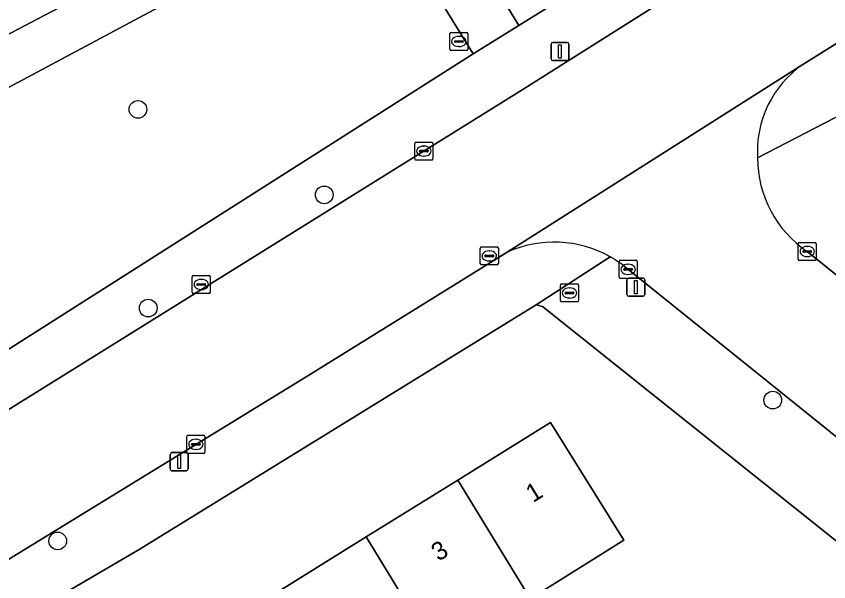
# Model space of a CAD drawing. Extents: x 159674 to 160531, y 382172 to 382904.
# Drawn here: x 160238.74 to 160283.66, y 382711.06 to 382742.32 of the extents above; entities that cross this region are included whole.
import ezdxf

# ---------------------------------------------------------------- set-up
doc = ezdxf.new("R2010")
doc.units = 0
for name, color, linetype in [('IMGEO_Boom', 7, 'Continuous'), ('IMGEO_Brandkraan', 7, 'Continuous'), ('IMGEO_Erf', 7, 'Continuous'), ('IMGEO_Groenvoorziening', 7, 'Continuous'), ('IMGEO_Kolk', 7, 'Continuous'), ('IMGEO_Lichtmast', 7, 'Continuous'), ('IMGEO_Pand', 7, 'Continuous'), ('IMGEO_Pand_nummerreeks', 7, 'Continuous'), ('IMGEO_Rijbaan_lokaal_open', 7, 'Continuous'), ('IMGEO_Rioolput', 7, 'Continuous'), ('IMGEO_Voetpad_halfverhard', 7, 'Continuous'), ('IMGEO_Voetpad_open', 7, 'Continuous')]:
    doc.layers.add(name, color=color, linetype=linetype)

msp = doc.modelspace()

# ---------------------------------------------------------------- linework, layer by layer
at = {"layer": 'IMGEO_Boom'}
for centre in [(160245.468, 382737.168), (160255.767, 382732.442), (160246.035, 382726.184), (160280.566, 382721.097), (160241.031, 382713.312)]:
    msp.add_circle(centre, 0.489, dxfattribs=at)
at = {"layer": 'IMGEO_Brandkraan'}
for p, q in [((160268.827, 382726.596), (160268.827, 382727.448)), ((160268.902, 382727.522), (160269.754, 382727.522)), ((160269.828, 382727.448), (160269.828, 382726.596)), ((160269.086, 382727.016), (160269.086, 382727.028)), ((160269.524, 382726.979), (160269.126, 382726.979)), ((160269.129, 382727.065), (160269.527, 382727.065)), ((160269.315, 382727.302), (160269.34, 382727.302)), ((160269.57, 382727.028), (160269.57, 382727.016)), ((160269.754, 382726.522), (160268.902, 382726.522)), ((160269.338, 382726.742), (160269.313, 382726.742))]:
    msp.add_line(p, q, dxfattribs=at)
for points in [[(160268.827, 382726.596), (160268.827, 382727.448)], [(160268.902, 382727.522), (160269.754, 382727.522)], [(160269.828, 382727.448), (160269.828, 382726.596)], [(160269.754, 382726.522), (160268.902, 382726.522)]]:
    msp.add_lwpolyline(points, dxfattribs=at)
for centre, radius, start, end in [((160268.904, 382727.446), 0.0765, 91.552, 178.448), ((160268.904, 382727.446), 0.0765, 91.552, 178.448), ((160269.752, 382727.446), 0.0765, 1.552, 88.448), ((160269.752, 382727.446), 0.0765, 1.552, 88.448), ((160269.126, 382727.025), 0.0403, 85.8775, 175.7526), ((160269.123, 382727.015), 0.0366, 178.938, 274.7102), ((160269.527, 382727.022), 0.043, 264.8664, 352.4533), ((160269.531, 382727.027), 0.0386, 1.7309, 96.639), ((160268.904, 382726.598), 0.0765, 181.552, 268.448), ((160268.904, 382726.598), 0.0765, 181.552, 268.448), ((160269.752, 382726.598), 0.0765, 271.552, 358.448), ((160269.752, 382726.598), 0.0765, 271.552, 358.448)]:
    msp.add_arc(centre, radius, start, end, dxfattribs=at)
for centre, major_axis, ratio, start_param, end_param in [((160269.314, 382727.022), (-0.387, 0.002), 0.722429, 4.712389, 7.853982), ((160269.339, 382727.022), (-0.39, 0.002), 0.717154, 1.570796, 4.712389)]:
    msp.add_ellipse(centre, major_axis=major_axis, ratio=ratio, start_param=start_param, end_param=end_param, dxfattribs=at)
at = {"layer": 'IMGEO_Erf'}
for points in [[(160263.63, 382697.299), (160266.891, 382692.05), (160272.972, 382696.028), (160269.707, 382701.284), (160271.793, 382702.58), (160273.825, 382703.842), (160277.09, 382698.586), (160280.422, 382700.656), (160288.011, 382710.171), (160267.842, 382726.279), (160267.481, 382726.359), (160260.898, 382722.304), (160245.542, 382712.846), (160232.632, 382705.313), (160223.268, 382700.381)], [(160237.854, 382700.968), (160242.783, 382704.03), (160247.804, 382707.149), (160252.846, 382710.282), (160258.092, 382713.54), (160263.149, 382716.682), (160268.281, 382719.87), (160272.331, 382713.35), (160268.084, 382710.712), (160267.16, 382710.138), (160270.635, 382704.465), (160267.317, 382702.401), (160263.802, 382708.052), (160262.075, 382706.979), (160256.874, 382703.748), (160251.809, 382700.602), (160246.834, 382697.511), (160241.905, 382694.449), (160242.971, 382692.734), (160241.022, 382691.523), (160242.806, 382688.652), (160239.401, 382686.46), (160237.89, 382688.94)]]:
    msp.add_lwpolyline(points, dxfattribs=at)
at = {"layer": 'IMGEO_Groenvoorziening'}
for points in [[(160200.052, 382762.134), (160192.129, 382756.282), (160195.593, 382750), (160208.869, 382725.922), (160242.298, 382743.421), (160241.058, 382745.734), (160249.38, 382750), (160254.327, 382752.536), (160259.322, 382755.576)], [(160260.129, 382752.312), (160261.537, 382750), (160266.528, 382741.805), (160279.619, 382749.944), (160271.52, 382762.171)], [(160263.993, 382740.23), (160259.263, 382747.922), (160257.112, 382748.44), (160230.735, 382734.341), (160210.172, 382723.685), (160216.913, 382712.097)], [(160237.605, 382723.468), (160263.993, 382740.23)]]:
    msp.add_lwpolyline(points, dxfattribs=at)
at = {"layer": 'IMGEO_Kolk'}
for p, q in [((160260.776, 382734.437), (160260.776, 382735.289)), ((160260.851, 382735.363), (160261.703, 382735.363)), ((160261.264, 382735.143), (160261.289, 382735.143)), ((160261.777, 382735.289), (160261.777, 382734.437)), ((160261.035, 382734.857), (160261.035, 382734.869)), ((160261.473, 382734.82), (160261.075, 382734.82)), ((160261.078, 382734.906), (160261.476, 382734.906)), ((160261.287, 382734.583), (160261.262, 382734.583)), ((160261.519, 382734.869), (160261.519, 382734.857)), ((160261.703, 382734.363), (160260.851, 382734.363)), ((160281.972, 382728.888), (160281.972, 382729.74)), ((160282.047, 382729.814), (160282.899, 382729.814)), ((160282.973, 382729.74), (160282.973, 382728.888)), ((160264.393, 382728.643), (160264.393, 382729.495)), ((160264.468, 382729.569), (160265.32, 382729.569)), ((160264.881, 382729.349), (160264.906, 382729.349)), ((160265.394, 382729.495), (160265.394, 382728.643)), ((160282.231, 382729.308), (160282.231, 382729.32)), ((160282.669, 382729.271), (160282.271, 382729.271)), ((160282.274, 382729.357), (160282.672, 382729.357)), ((160282.46, 382729.594), (160282.485, 382729.594)), ((160282.715, 382729.32), (160282.715, 382729.308)), ((160264.652, 382729.063), (160264.652, 382729.075)), ((160265.09, 382729.026), (160264.692, 382729.026)), ((160264.695, 382729.112), (160265.093, 382729.112)), ((160264.904, 382728.789), (160264.879, 382728.789)), ((160265.136, 382729.075), (160265.136, 382729.063)), ((160272.066, 382727.902), (160272.066, 382728.754)), ((160272.141, 382728.828), (160272.993, 382728.828)), ((160273.067, 382728.754), (160273.067, 382727.902)), ((160282.899, 382728.814), (160282.047, 382728.814)), ((160282.483, 382729.034), (160282.458, 382729.034)), ((160265.32, 382728.569), (160264.468, 382728.569)), ((160272.325, 382728.322), (160272.325, 382728.334)), ((160272.763, 382728.285), (160272.365, 382728.285)), ((160272.368, 382728.371), (160272.766, 382728.371)), ((160272.554, 382728.608), (160272.579, 382728.608)), ((160272.809, 382728.334), (160272.809, 382728.322)), ((160248.468, 382727.065), (160248.468, 382727.917)), ((160248.543, 382727.991), (160249.395, 382727.991)), ((160249.469, 382727.917), (160249.469, 382727.065)), ((160272.993, 382727.828), (160272.141, 382727.828)), ((160272.577, 382728.048), (160272.552, 382728.048)), ((160248.727, 382727.485), (160248.727, 382727.497)), ((160249.165, 382727.448), (160248.767, 382727.448)), ((160248.77, 382727.534), (160249.168, 382727.534)), ((160248.956, 382727.771), (160248.981, 382727.771)), ((160249.211, 382727.497), (160249.211, 382727.485)), ((160249.395, 382726.991), (160248.543, 382726.991)), ((160248.979, 382727.211), (160248.954, 382727.211)), ((160248.172, 382718.226), (160248.172, 382719.078)), ((160248.247, 382719.152), (160249.099, 382719.152)), ((160248.66, 382718.932), (160248.685, 382718.932)), ((160249.173, 382719.078), (160249.173, 382718.226)), ((160248.431, 382718.646), (160248.431, 382718.658)), ((160248.869, 382718.609), (160248.471, 382718.609)), ((160248.474, 382718.695), (160248.872, 382718.695)), ((160248.683, 382718.372), (160248.658, 382718.372)), ((160248.915, 382718.658), (160248.915, 382718.646)), ((160249.099, 382718.152), (160248.247, 382718.152))]:
    msp.add_line(p, q, dxfattribs=at)
for points in [[(160260.776, 382734.437), (160260.776, 382735.289)], [(160260.851, 382735.363), (160261.703, 382735.363)], [(160261.777, 382735.289), (160261.777, 382734.437)], [(160261.703, 382734.363), (160260.851, 382734.363)], [(160281.972, 382728.888), (160281.972, 382729.74)], [(160282.047, 382729.814), (160282.899, 382729.814)], [(160282.973, 382729.74), (160282.973, 382728.888)], [(160264.393, 382728.643), (160264.393, 382729.495)], [(160264.468, 382729.569), (160265.32, 382729.569)], [(160265.394, 382729.495), (160265.394, 382728.643)], [(160272.066, 382727.902), (160272.066, 382728.754)], [(160272.141, 382728.828), (160272.993, 382728.828)], [(160273.067, 382728.754), (160273.067, 382727.902)], [(160282.899, 382728.814), (160282.047, 382728.814)], [(160265.32, 382728.569), (160264.468, 382728.569)], [(160248.468, 382727.065), (160248.468, 382727.917)], [(160248.543, 382727.991), (160249.395, 382727.991)], [(160249.469, 382727.917), (160249.469, 382727.065)], [(160272.993, 382727.828), (160272.141, 382727.828)], [(160249.395, 382726.991), (160248.543, 382726.991)], [(160248.172, 382718.226), (160248.172, 382719.078)], [(160248.247, 382719.152), (160249.099, 382719.152)], [(160249.173, 382719.078), (160249.173, 382718.226)], [(160249.099, 382718.152), (160248.247, 382718.152)]]:
    msp.add_lwpolyline(points, dxfattribs=at)
for centre, radius, start, end in [((160260.853, 382735.287), 0.0765, 91.552, 178.448), ((160260.853, 382735.287), 0.0765, 91.552, 178.448), ((160261.701, 382735.287), 0.0765, 1.552, 88.448), ((160261.701, 382735.287), 0.0765, 1.552, 88.448), ((160261.075, 382734.866), 0.0403, 85.8775, 175.7526), ((160261.072, 382734.856), 0.0366, 178.938, 274.7102), ((160261.476, 382734.863), 0.043, 264.8664, 352.4533), ((160261.48, 382734.868), 0.0386, 1.7309, 96.639), ((160260.853, 382734.439), 0.0765, 181.552, 268.448), ((160260.853, 382734.439), 0.0765, 181.552, 268.448), ((160261.701, 382734.439), 0.0765, 271.552, 358.448), ((160261.701, 382734.439), 0.0765, 271.552, 358.448), ((160282.049, 382729.738), 0.0765, 91.552, 178.448), ((160282.049, 382729.738), 0.0765, 91.552, 178.448), ((160282.897, 382729.738), 0.0765, 1.552, 88.448), ((160282.897, 382729.738), 0.0765, 1.552, 88.448), ((160264.47, 382729.493), 0.0765, 91.552, 178.448), ((160264.47, 382729.493), 0.0765, 91.552, 178.448), ((160265.318, 382729.493), 0.0765, 1.552, 88.448), ((160265.318, 382729.493), 0.0765, 1.552, 88.448), ((160282.271, 382729.317), 0.0403, 85.8775, 175.7526), ((160282.268, 382729.307), 0.0366, 178.938, 274.7102), ((160282.672, 382729.314), 0.043, 264.8664, 352.4533), ((160282.676, 382729.319), 0.0386, 1.7309, 96.639), ((160264.692, 382729.072), 0.0403, 85.8775, 175.7526), ((160264.689, 382729.062), 0.0366, 178.938, 274.7102), ((160265.093, 382729.069), 0.043, 264.8664, 352.4533), ((160265.097, 382729.074), 0.0386, 1.7309, 96.639), ((160272.143, 382728.752), 0.0765, 91.552, 178.448), ((160272.143, 382728.752), 0.0765, 91.552, 178.448), ((160272.991, 382728.752), 0.0765, 1.552, 88.448), ((160272.991, 382728.752), 0.0765, 1.552, 88.448), ((160282.049, 382728.89), 0.0765, 181.552, 268.448), ((160282.049, 382728.89), 0.0765, 181.552, 268.448), ((160282.897, 382728.89), 0.0765, 271.552, 358.448), ((160282.897, 382728.89), 0.0765, 271.552, 358.448), ((160264.47, 382728.645), 0.0765, 181.552, 268.448), ((160264.47, 382728.645), 0.0765, 181.552, 268.448), ((160265.318, 382728.645), 0.0765, 271.552, 358.448), ((160265.318, 382728.645), 0.0765, 271.552, 358.448), ((160272.365, 382728.331), 0.0403, 85.8775, 175.7526), ((160272.362, 382728.321), 0.0366, 178.938, 274.7102), ((160272.766, 382728.328), 0.043, 264.8664, 352.4533), ((160272.77, 382728.333), 0.0386, 1.7309, 96.639), ((160248.545, 382727.915), 0.0765, 91.552, 178.448), ((160248.545, 382727.915), 0.0765, 91.552, 178.448), ((160249.393, 382727.915), 0.0765, 1.552, 88.448), ((160249.393, 382727.915), 0.0765, 1.552, 88.448), ((160272.143, 382727.904), 0.0765, 181.552, 268.448), ((160272.143, 382727.904), 0.0765, 181.552, 268.448), ((160272.991, 382727.904), 0.0765, 271.552, 358.448), ((160272.991, 382727.904), 0.0765, 271.552, 358.448), ((160248.767, 382727.494), 0.0403, 85.8775, 175.7526), ((160248.764, 382727.484), 0.0366, 178.938, 274.7102), ((160249.168, 382727.491), 0.043, 264.8664, 352.4533), ((160249.172, 382727.496), 0.0386, 1.7309, 96.639), ((160248.545, 382727.067), 0.0765, 181.552, 268.448), ((160248.545, 382727.067), 0.0765, 181.552, 268.448), ((160249.393, 382727.067), 0.0765, 271.552, 358.448), ((160249.393, 382727.067), 0.0765, 271.552, 358.448), ((160248.249, 382719.076), 0.0765, 91.552, 178.448), ((160248.249, 382719.076), 0.0765, 91.552, 178.448), ((160249.097, 382719.076), 0.0765, 1.552, 88.448), ((160249.097, 382719.076), 0.0765, 1.552, 88.448), ((160248.471, 382718.655), 0.0403, 85.8775, 175.7526), ((160248.468, 382718.645), 0.0366, 178.938, 274.7102), ((160248.872, 382718.652), 0.043, 264.8664, 352.4533), ((160248.876, 382718.657), 0.0386, 1.7309, 96.639), ((160248.249, 382718.228), 0.0765, 181.552, 268.448), ((160248.249, 382718.228), 0.0765, 181.552, 268.448), ((160249.097, 382718.228), 0.0765, 271.552, 358.448), ((160249.097, 382718.228), 0.0765, 271.552, 358.448)]:
    msp.add_arc(centre, radius, start, end, dxfattribs=at)
for centre, major_axis, ratio, start_param, end_param in [((160261.263, 382734.863), (-0.387, 0.002), 0.722429, 4.712389, 7.853982), ((160261.288, 382734.863), (-0.39, 0.002), 0.717154, 1.570796, 4.712389), ((160264.88, 382729.069), (-0.387, 0.002), 0.722429, 4.712389, 7.853982), ((160264.905, 382729.069), (-0.39, 0.002), 0.717154, 1.570796, 4.712389), ((160282.459, 382729.314), (-0.387, 0.002), 0.722429, 4.712389, 7.853982), ((160282.484, 382729.314), (-0.39, 0.002), 0.717154, 1.570796, 4.712389), ((160272.553, 382728.328), (-0.387, 0.002), 0.722429, 4.712389, 7.853982), ((160272.578, 382728.328), (-0.39, 0.002), 0.717154, 1.570796, 4.712389), ((160248.955, 382727.491), (-0.387, 0.002), 0.722429, 4.712389, 7.853982), ((160248.98, 382727.491), (-0.39, 0.002), 0.717154, 1.570796, 4.712389), ((160248.659, 382718.652), (-0.387, 0.002), 0.722429, 4.712389, 7.853982), ((160248.684, 382718.652), (-0.39, 0.002), 0.717154, 1.570796, 4.712389)]:
    msp.add_ellipse(centre, major_axis=major_axis, ratio=ratio, start_param=start_param, end_param=end_param, dxfattribs=at)
at = {"layer": 'IMGEO_Lichtmast'}
for p, q in [((160268.405, 382740.867), (160269.195, 382740.867)), ((160269.195, 382740.867), (160268.405, 382740.867)), ((160268.305, 382739.967), (160268.305, 382740.767)), ((160268.305, 382740.767), (160268.305, 382739.967)), ((160269.295, 382740.767), (160269.295, 382739.967)), ((160269.295, 382739.967), (160269.295, 382740.767)), ((160269.195, 382739.867), (160268.405, 382739.867)), ((160268.405, 382739.867), (160269.195, 382739.867)), ((160272.602, 382727.841), (160273.392, 382727.841)), ((160273.392, 382727.841), (160272.602, 382727.841)), ((160272.502, 382726.941), (160272.502, 382727.741)), ((160272.502, 382727.741), (160272.502, 382726.941)), ((160273.492, 382727.741), (160273.492, 382726.941)), ((160273.492, 382726.941), (160273.492, 382727.741)), ((160273.392, 382726.841), (160272.602, 382726.841)), ((160272.602, 382726.841), (160273.392, 382726.841)), ((160247.249, 382717.298), (160247.249, 382718.098)), ((160247.249, 382718.098), (160247.249, 382717.298)), ((160247.349, 382718.198), (160248.139, 382718.198)), ((160248.139, 382718.198), (160247.349, 382718.198)), ((160248.239, 382718.098), (160248.239, 382717.298)), ((160248.239, 382717.298), (160248.239, 382718.098)), ((160248.139, 382717.198), (160247.349, 382717.198)), ((160247.349, 382717.198), (160248.139, 382717.198))]:
    msp.add_line(p, q, dxfattribs=at)
for points in [[(160268.725, 382740.742), (160268.875, 382740.742), (160268.875, 382739.992), (160268.725, 382739.992), (160268.725, 382740.742)], [(160272.922, 382727.716), (160273.072, 382727.716), (160273.072, 382726.966), (160272.922, 382726.966), (160272.922, 382727.716)], [(160247.669, 382718.073), (160247.819, 382718.073), (160247.819, 382717.323), (160247.669, 382717.323), (160247.669, 382718.073)]]:
    msp.add_lwpolyline(points, dxfattribs=at)
for centre, start, end in [((160268.405, 382740.767), 90, 180), ((160268.405, 382740.767), 90, 180), ((160269.195, 382740.767), 0, 90), ((160269.195, 382740.767), 360, 90), ((160268.405, 382739.967), 180, 270), ((160268.405, 382739.967), 180, 270), ((160269.195, 382739.967), 270, 0), ((160269.195, 382739.967), 270, 0), ((160272.602, 382727.741), 90, 180), ((160272.602, 382727.741), 90, 180), ((160273.392, 382727.741), 0, 90), ((160273.392, 382727.741), 360, 90), ((160272.602, 382726.941), 180, 270), ((160272.602, 382726.941), 180, 270), ((160273.392, 382726.941), 270, 0), ((160273.392, 382726.941), 270, 0), ((160247.349, 382718.098), 90, 180), ((160247.349, 382718.098), 90, 180), ((160248.139, 382718.098), 0, 90), ((160248.139, 382718.098), 360, 90), ((160247.349, 382717.298), 180, 270), ((160247.349, 382717.298), 180, 270), ((160248.139, 382717.298), 270, 0), ((160248.139, 382717.298), 270, 0)]:
    msp.add_arc(centre, 0.1, start, end, dxfattribs=at)
at = {"layer": 'IMGEO_Pand'}
for points in [[(160263.149, 382716.682), (160267.16, 382710.138), (160268.084, 382710.712), (160272.331, 382713.35), (160268.281, 382719.87)], [(160258.092, 382713.54), (160262.075, 382706.979), (160263.802, 382708.052), (160267.317, 382702.401), (160270.635, 382704.465), (160267.16, 382710.138), (160263.149, 382716.682)], [(160258.092, 382713.54), (160252.846, 382710.282), (160256.874, 382703.748), (160262.075, 382706.979)]]:
    msp.add_lwpolyline(points, close=True, dxfattribs=at)
at = {"layer": 'IMGEO_Rijbaan_lokaal_open'}
for points in [[(160369.756, 382802.778), (160366.508, 382800.739), (160365.277, 382799.977), (160347.87, 382789.101), (160333.21, 382779.724), (160319.266, 382771.031), (160285.322, 382750), (160266.649, 382738.205), (160233.3, 382717.459)], [(160188.447, 382696.325), (160181.888, 382694.035), (160183.725, 382687.281), (160193.069, 382690.742), (160201.751, 382694.067), (160212.586, 382698.728), (160220.039, 382702.396), (160236.066, 382710.925), (160254.768, 382722.388), (160265.882, 382729.271), (160282.226, 382739.647), (160298.781, 382750), (160329.129, 382768.971)], [(160282.226, 382739.647), (160265.882, 382729.271)], [(160272.341, 382728.51), (160285.523, 382717.905), (160289.879, 382723.36), (160282.47, 382729.315)]]:
    msp.add_lwpolyline(points, dxfattribs=at)
for centre, radius, start, end in [((160285.57, 382734.84), 5.855, 124.8233, 183.4587), ((160285.953, 382734.478), 6.228, 179.919, 235.9946), ((160268.479, 382723.522), 6.308, 60.6229, 114.3062), ((160268.525, 382723.586), 6.229, 52.2239, 60.7064)]:
    msp.add_arc(centre, radius, start, end, dxfattribs=at)
at = {"layer": 'IMGEO_Rioolput'}
for p, q in [((160262.712, 382740.497), (160262.712, 382741.349)), ((160262.787, 382741.423), (160263.639, 382741.423)), ((160263.713, 382741.349), (160263.713, 382740.497)), ((160262.971, 382740.917), (160262.971, 382740.929)), ((160263.409, 382740.88), (160263.011, 382740.88)), ((160263.014, 382740.966), (160263.412, 382740.966)), ((160263.2, 382741.203), (160263.225, 382741.203)), ((160263.455, 382740.929), (160263.455, 382740.917)), ((160263.639, 382740.423), (160262.787, 382740.423)), ((160263.223, 382740.643), (160263.198, 382740.643))]:
    msp.add_line(p, q, dxfattribs=at)
for points in [[(160262.712, 382740.497), (160262.712, 382741.349)], [(160262.787, 382741.423), (160263.639, 382741.423)], [(160263.713, 382741.349), (160263.713, 382740.497)], [(160263.639, 382740.423), (160262.787, 382740.423)]]:
    msp.add_lwpolyline(points, dxfattribs=at)
for centre, radius, start, end in [((160262.789, 382741.347), 0.0765, 91.552, 178.448), ((160262.789, 382741.347), 0.0765, 91.552, 178.448), ((160263.637, 382741.347), 0.0765, 1.552, 88.448), ((160263.637, 382741.347), 0.0765, 1.552, 88.448), ((160263.011, 382740.926), 0.0403, 85.8775, 175.7526), ((160263.008, 382740.916), 0.0366, 178.938, 274.7102), ((160263.412, 382740.923), 0.043, 264.8664, 352.4533), ((160263.416, 382740.928), 0.0386, 1.7309, 96.639), ((160262.789, 382740.499), 0.0765, 181.552, 268.448), ((160262.789, 382740.499), 0.0765, 181.552, 268.448), ((160263.637, 382740.499), 0.0765, 271.552, 358.448), ((160263.637, 382740.499), 0.0765, 271.552, 358.448)]:
    msp.add_arc(centre, radius, start, end, dxfattribs=at)
for centre, major_axis, ratio, start_param, end_param in [((160263.199, 382740.923), (-0.387, 0.002), 0.722429, 4.712389, 7.853982), ((160263.224, 382740.923), (-0.39, 0.002), 0.717154, 1.570796, 4.712389)]:
    msp.add_ellipse(centre, major_axis=major_axis, ratio=ratio, start_param=start_param, end_param=end_param, dxfattribs=at)
at = {"layer": 'IMGEO_Voetpad_halfverhard'}
for points in [[(160259.322, 382755.576), (160254.327, 382752.536), (160249.38, 382750), (160241.058, 382745.734), (160242.298, 382743.421), (160208.869, 382725.922), (160200.293, 382721.433)], [(160200.923, 382718.842), (160210.172, 382723.685), (160230.735, 382734.341), (160257.112, 382748.44), (160259.263, 382747.922), (160263.993, 382740.23), (160266.528, 382741.805), (160261.537, 382750), (160260.129, 382752.312)]]:
    msp.add_lwpolyline(points, dxfattribs=at)
at = {"layer": 'IMGEO_Voetpad_open'}
for points in [[(160409.327, 382827.356), (160372.665, 382804.367), (160368.285, 382805.376), (160357.09, 382798.388), (160346.544, 382791.581), (160279.71, 382750), (160279.619, 382749.944), (160266.528, 382741.805), (160263.993, 382740.23), (160237.605, 382723.468)], [(160357.866, 382782.856), (160358.012, 382782.948), (160356.181, 382785.891), (160351.956, 382783.239), (160334.603, 382772.418), (160329.129, 382768.971), (160298.781, 382750), (160282.226, 382739.647)], [(160279.725, 382734.487), (160285.03, 382737.24), (160305.531, 382750), (160357.866, 382782.856)], [(160233.3, 382717.459), (160266.649, 382738.205), (160285.322, 382750), (160319.266, 382771.031), (160333.21, 382779.724)], [(160285.03, 382737.24), (160279.725, 382734.487)], [(160265.882, 382729.271), (160254.768, 382722.388), (160236.066, 382710.925), (160220.039, 382702.396), (160212.586, 382698.728), (160201.751, 382694.067), (160193.069, 382690.742), (160183.725, 382687.281)], [(160282.47, 382729.315), (160289.879, 382723.36), (160292.249, 382721.456), (160329.213, 382691.747), (160331.172, 382690.173), (160331.562, 382689.859), (160344.376, 382679.555), (160359.84, 382667.121), (160360.67, 382668.154), (160361.649, 382667.367), (160363.734, 382669.962), (160363.603, 382670.069), (160359.987, 382672.384), (160357.009, 382674.758), (160346.941, 382682.927)], [(160223.268, 382700.381), (160232.632, 382705.313), (160245.542, 382712.846), (160260.898, 382722.304), (160267.481, 382726.359), (160271.573, 382729.019)], [(160271.573, 382729.019), (160267.481, 382726.359), (160267.842, 382726.279), (160288.011, 382710.171), (160289.223, 382709.204), (160306.664, 382695.275), (160309.343, 382693.001), (160313.249, 382689.912), (160316.257, 382687.487), (160332.815, 382674.214), (160337.911, 382673.579)], [(160287.892, 382716), (160285.523, 382717.905), (160272.341, 382728.51)]]:
    msp.add_lwpolyline(points, dxfattribs=at)
for centre, radius, start, end in [((160285.57, 382734.84), 5.855, 124.8233, 183.4587), ((160285.953, 382734.478), 6.228, 179.919, 235.9946), ((160268.479, 382723.522), 6.308, 60.6229, 114.3062), ((160268.525, 382723.586), 6.229, 52.2239, 60.7064)]:
    msp.add_arc(centre, radius, start, end, dxfattribs=at)

# ---------------------------------------------------------------- texts
at = {"layer": 'IMGEO_Pand_nummerreeks'}
for s, p in [('1', (160267.31, 382715.406)), ('3', (160262.086, 382712.161))]:
    msp.add_text(s, height=1, rotation=31.8493, dxfattribs=at).set_placement(p)

doc.saveas('drawing.dxf')
